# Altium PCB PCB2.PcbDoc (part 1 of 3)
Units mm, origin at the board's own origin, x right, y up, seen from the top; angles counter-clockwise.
Board outline 277.37 x 238.38 mm, 2 copper layers (Top Layer, Bottom Layer); 139 components, 149 nets, 593 pads, 86 vias.
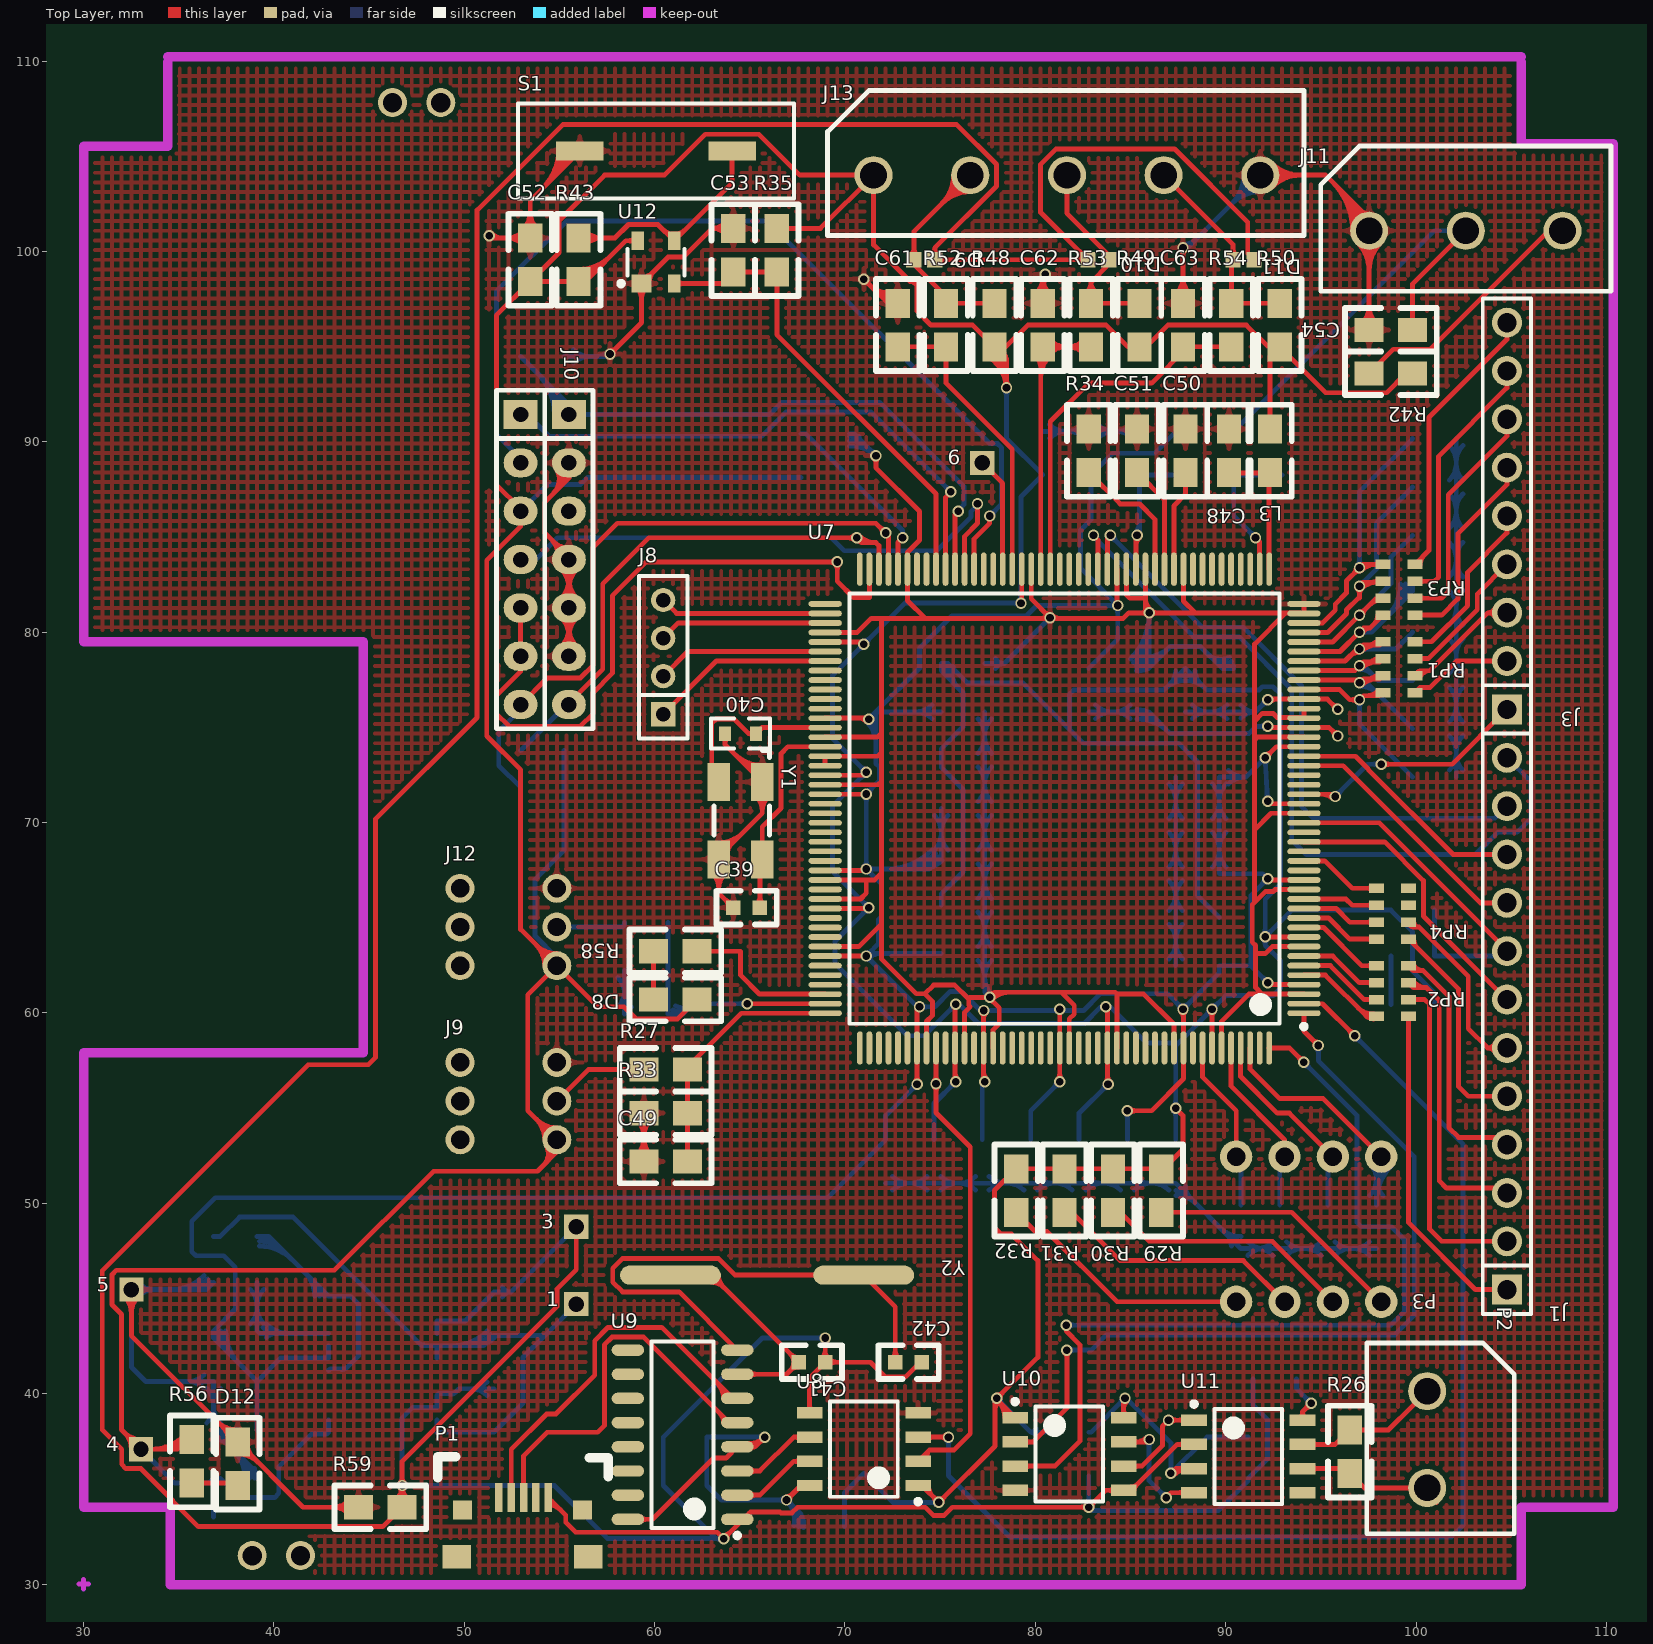
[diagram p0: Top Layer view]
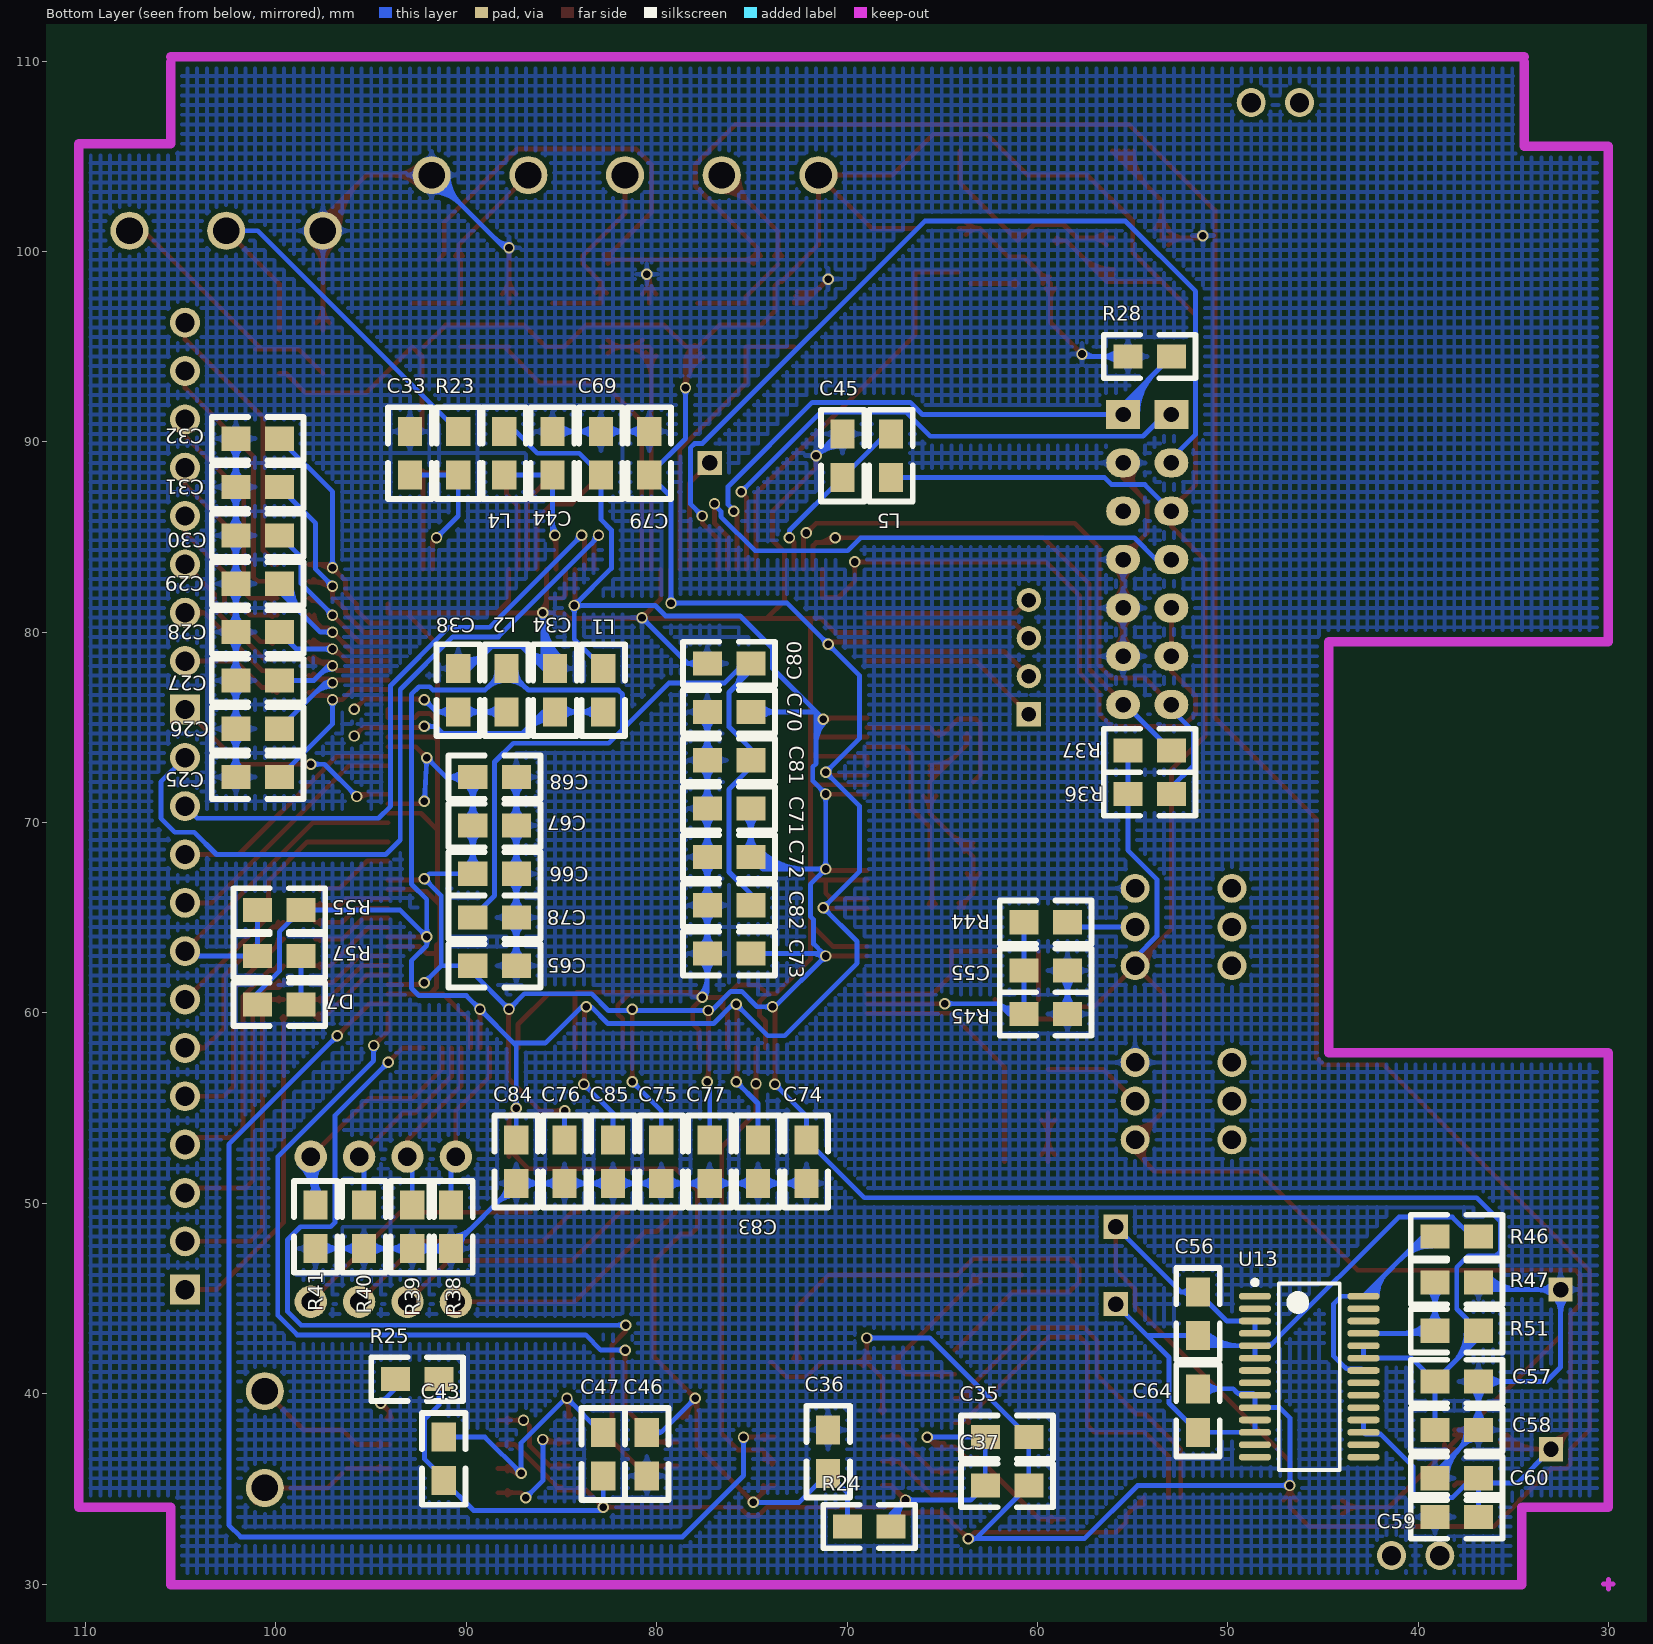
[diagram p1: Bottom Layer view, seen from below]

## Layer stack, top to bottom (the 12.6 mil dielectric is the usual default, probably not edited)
Top Layer: signal copper 0.0356
Dielectric: dielectric 0.32, FR-4, Dk 4.8
Bottom Layer: signal copper 0.0356

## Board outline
23.749,236.601 26.162,239.014 295.021,239.014 295.021,1.778 293.878,0.635 282.956,11.557 17.653,11.557

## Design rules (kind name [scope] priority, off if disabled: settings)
Clearance [All] p1: gap=0.254
PolygonConnect [All] p1: connectstyle=Relief reliefconductorwidth=0.254 reliefentries=4 polygonreliefangle="90 Angle"
RoutingVias [All] p1: holewidth=0.711 width=1.27 viastyle="Through Hole" minholewidth=0.711 minwidth=1.27 maxholewidth=0.711 maxwidth=1.27
SilkscreenOverComponentPads [All] p1: minsilkscreentomaskgap=0.254
SolderMaskExpansion [All] p1: expansion=0.102
Width [All] p1: maxlimit=0.254 minlimit=0.254 preferedwidth=0.254
27 further rules are at their usual default settings.

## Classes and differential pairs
component class Sheet1: 1 2 3 C1 C2 C3 C4 C5 C6 C7 C8 C9 C10 C11 C12 C13 C14 C15 C16 C17 C18 C19 C20 C21 C22 C23 C24 D1 D2 D3 D4 D5 D6 J1 J2 J3 J4 Q1 R1 R2 R3 R4 R5 R6 R7 R8 R9 R10 R11 R12 R13 R14 R15 R16 R17 R18 R19 R20 R21 R22 U1 U2 U3 U4 U5 U6

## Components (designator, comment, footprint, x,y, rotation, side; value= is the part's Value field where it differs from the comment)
1 "SIP1" sip-1 55.88,44.704 r90 top
3 "SIP1" sip-1 55.88,48.768 r90 top
4 "SIP1" sip-1 33.02,37.084 r90 top
5 "SIP1" sip-1 32.512,45.466 r90 top
6 "SIP1" sip-1 77.216,88.9 r270 top
C25 "Cap" 0805 102.108,72.39 r180 bottom
C26 "Cap" 0805 102.108,74.93 r180 bottom
C27 "Cap" 0805 99.822,77.47 r0 bottom
C28 "Cap" 0805 102.108,80.01 r180 bottom
C29 "Cap" 0805 102.108,82.55 r180 bottom
C30 "Cap" 0805 102.108,85.09 r180 bottom
C31 "Cap" 0805 102.108,87.63 r180 bottom
C32 "Cap" 0805 102.108,90.17 r180 bottom
C33 "Cap" 0805 92.964,90.551 r270 bottom
C34 "Cap" 0805 85.344,75.819 r90 bottom
C35 "Cap" 0805 62.738,37.719 r180 bottom
C36 "Cap" 0805 70.993,38.1 r270 bottom
C37 "Cap" 0805 62.738,35.179 r180 bottom
C38 "Cap" 0805 90.424,78.105 r270 bottom
C39 "Cap" 0603 65.532,65.532 r180 top
C40 "Cap" 0603R 64.516,74.676 r180 top
C41 "Cap" 0603 68.961,41.656 r180 top
C42 "Cap" 0603 74.041,41.656 r180 top
C43 "Cap" 0805 91.186,37.719 r270 bottom
C44 "Cap" 0805 85.471,90.551 r270 bottom
C45 "Cap" 0805 70.231,88.138 r90 bottom
C46 "Cap" 0805 80.518,35.687 r90 bottom
C47 "Cap" 0805 82.804,37.973 r270 bottom
C48 "Cap" 0805 90.17,90.678 r270 top
C49 "Cap" 0805 59.436,52.197 r0 top
C50 "Cap Pol1" 0805 87.884,88.392 r90 top
C51 "Cap Pol1" 0805 85.344,88.392 r90 top
C52 "Cap" 0805 53.467,98.425 r90 top
C53 "Cap" 0805 64.135,101.219 r270 top
C54 "Cap" 0805 97.536,95.885 r0 top
C55 "Cap" 0805 58.42,62.23 r0 bottom
C56 "Cap" 0805 51.562,45.339 r270 bottom
C57 "Cap" 0805 39.116,40.64 r180 bottom
C58 "Cap" 0805 36.83,38.1 r0 bottom
C59 "Cap" 0805 39.116,33.528 r180 bottom
C60 "Cap" 0805 39.116,35.56 r180 bottom
C61 "Cap" 0805 72.771,97.282 r270 top
C62 "Cap" 0805 80.391,97.282 r270 top
C63 "Cap" 0805 87.757,97.282 r270 top
C64 "Cap" 0805 51.562,40.259 r270 bottom
C65 "Cap" 0805 89.662,62.484 r180 bottom
C66 "Cap" 0805 87.376,67.31 r0 bottom
C67 "Cap" 0805 87.376,69.85 r0 bottom
C68 "Cap" 0805 89.662,72.39 r180 bottom
C69 "Cap" 0805 82.931,90.551 r270 bottom
C70 "Cap" 0805 77.343,75.819 r180 bottom
C71 "Cap" 0805 77.343,70.739 r180 bottom
C72 "Cap" 0805 77.343,68.199 r180 bottom
C73 "Cap" 0805 77.343,63.119 r180 bottom
C74 "Cap" 0805 72.136,51.054 r90 bottom
C75 "Cap" 0805 79.756,51.054 r90 bottom
C76 "Cap" 0805 84.836,51.054 r90 bottom
C77 "Cap" 0805 77.216,51.054 r90 bottom
C78 "Cap" 0805 87.376,65.024 r0 bottom
C79 "Cap" 0805 80.391,90.551 r270 bottom
C80 "Cap" 0805 77.343,78.359 r180 bottom
C81 "Cap" 0805 77.343,73.279 r180 bottom
C82 "Cap" 0805 77.343,65.659 r180 bottom
C83 "Cap" 0805 74.676,51.054 r90 bottom
C84 "Cap" 0805 87.376,51.054 r90 bottom
C85 "Cap" 0805 82.296,51.054 r90 bottom
D7 "LED" 0805 100.965,60.452 r180 bottom
D8 "LED" 0805 62.23,60.706 r180 top
D9 "TPD1E10B06" 0402 74.168,99.568 r0 top
D10 "TPD1E10B06" 0402 83.312,99.568 r180 top
D11 "TPD1E10B06" 0402 90.932,99.568 r0 top
D12 "LED" 0805 38.1,35.179 r90 top
J1 "SIP12" SIP12-2.54 104.775,45.466 r90 top
J3 "SIP9" SIP9-2.54 104.775,75.946 r90 top
J8 "SIP4" SIP4-2.0 60.452,75.692 r90 top
J9 "HEADER3*1" zisuo 54.864,57.404 r270 top
J10 "JTAG" JTAG-14 55.499,91.44 r270 top
J11 "HEADER3*1" 5.0J-3 97.536,101.092 r0 top
J12 "HEADER3*1" zisuo 54.864,66.548 r270 top
J13 "header5" 5.0J-5 69.088,108.712 r0 top
L1 "Inductor" 0805 82.804,78.105 r270 bottom
L2 "Inductor" 0805 87.884,78.105 r270 bottom
L3 "Inductor" 0805 92.329,90.678 r270 top
L4 "Inductor" 0805 88.011,90.551 r270 bottom
L5 "Inductor" 0805 67.691,88.138 r90 bottom
P1 "micro" micro 51.816,34.544 r0 top
P2 "Header 2" 5.0J-2 105.156,42.672 r270 top
P3 "4p" 4P 90.551,52.451 r0 top
R23 "Res2" 0805 90.424,90.551 r270 bottom
R24 "Res2" 0805 69.977,33.02 r180 bottom
R25 "Res2" 0805 91.44,40.767 r0 bottom
R26 "Res2" 0805 96.52,35.814 r90 top
R27 "Res2" 0805 59.436,57.023 r0 top
R28 "Res2" 0805 52.959,94.488 r0 bottom
R29 "Res2" 0805 86.614,49.53 r90 top
R30 "Res2" 0805 84.074,49.53 r90 top
R31 "Res2" 0805 81.534,49.53 r90 top
R32 "Res2" 0805 78.994,49.53 r90 top
R33 "Res2" 0805 59.436,54.737 r0 top
R34 "Res2" 0805 82.804,90.678 r270 top
R35 "Res2" 0805 66.421,98.933 r90 top
R36 "Res2" 0805 55.245,71.501 r180 bottom
R37 "Res2" 0805 52.959,73.787 r0 bottom
R38 "Res2" 0805 90.805,47.625 r90 bottom
R39 "Res2" 0805 92.837,47.625 r90 bottom
R40 "Res2" 0805 95.377,47.625 r90 bottom
R41 "Res2" 0805 97.917,47.625 r90 bottom
R42 "Res2" 0805 97.536,93.599 r0 top
R43 "Res2" 0805 56.007,100.711 r270 top
R44 "Res2" 0805 58.42,64.77 r0 bottom
R45 "Res2" 0805 58.42,59.944 r0 bottom
R46 "Res2" 0805 39.116,48.26 r180 bottom
R47 "Res2" 0805 36.83,45.847 r0 bottom
R48 "Res2" 0805 77.851,97.282 r270 top
R49 "Res2" 0805 85.471,97.282 r270 top
R50 "Res2" 0805 92.837,97.282 r270 top
R51 "Res2" 0805 36.83,43.307 r0 bottom
R52 "Res2" 0805 75.311,97.282 r270 top
R53 "Res2" 0805 82.931,97.282 r270 top
R54 "Res2" 0805 90.297,97.282 r270 top
R55 "Res2" 0805 100.965,65.405 r180 bottom
R56 "Res2" 0805 35.687,35.306 r90 top
R57 "Res2" 0805 100.965,62.992 r180 bottom
R58 "Res2" 0805 62.23,63.246 r180 top
R59 "Res2" 0805 46.736,34.036 r180 top
RP1 "RP" 8P4R 99.06,78.232 r180 top
RP2 "RP" 8P4R 98.806,61.087 r0 top
RP3 "RP" 8P4R 99.06,82.296 r180 top
RP4 "RP" 8P4R 98.806,65.151 r0 top
S1 "switch" "switch - duplicate" 60.071,105.283 r180 top
U7 "TMS320F28335" PTP 81.534,70.739 r180 top
U8 "ISO7221" SO-8 70.993,37.084 r180 top
U9 "CH340G" SOP16 61.468,37.846 r180 top
U10 "ISO7221" SO-8 81.788,36.83 r0 top
U11 "SN65HVD230" SO-8 91.186,36.703 r0 top
U12 "MAX811" SOT143 60.071,99.441 r90 top
U13 "TPS767D301" TPS767 45.72,40.894 r180 bottom
Y1 "crystal" 5032 66.04,72.136 r270 top
Y2 "CRYSTAL" 49SMD 60.833,46.228 r0 top

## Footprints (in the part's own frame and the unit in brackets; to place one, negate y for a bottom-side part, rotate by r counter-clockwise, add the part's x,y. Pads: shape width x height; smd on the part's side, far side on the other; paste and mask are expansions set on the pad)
4P [mm]
  round 1.7 hole 0.97: 1(0,0) 2(2.54,0) 3(5.08,0) 4(7.62,0) 5(7.62,-7.62) 6(5.08,-7.62) 7(2.54,-7.62) 8(0,-7.62)
5.0J-2 [mm]
  round 2 hole 1.4: 1(2.54,-4.572) 2(7.62,-4.572)
  silkscreen extent 0,-7.75 10.03,0
5.0J-3 [mm]
  round 2 hole 1.4: 1(0,0) 2(5.08,0) 3(10.16,0)
  silkscreen extent -2.54,-3.17 12.7,4.44
5.0J-5 [mm]
  round 2 hole 1.4: 1(2.413,-4.699) 2(7.493,-4.699) 3(12.573,-4.699) 4(17.653,-4.699) 5(22.733,-4.699)
  silkscreen extent 0,-7.87 25.02,-0.25
8P4R [mm]
  rect 0.8x0.5 smd: 1(-0.889,1.397) 2(-0.889,0.508) 3(-0.889,-0.381) 4(-0.889,-1.27) 5(0.8,-1.27) 6(0.8,-0.381) 7(0.8,0.508) 8(0.8,1.397)
49SMD [mm]
  oval 5.3x1 smd: 1(0,0) 3(10.15,0)
0402 [mm] "Chip Resistor, 2-Leads, Body 1.0x0.6mm, IPC Medium Density"
  rect 0.8x0.8 smd: 1(-0.55,0) 2(0.55,0)
0603 [mil]
  rect 30x30 smd: 1(0,0) 2(55,0)
  silkscreen extent -35,-35 90,35
0603R [mil]
  rect 25x30 smd: 1(-32,0) 2(32,0)
  silkscreen extent -61,-31 61,31
0805 [mil]
  rect 60x50 smd: 1(0,0) 2(90,0)
  silkscreen extent -50,-45 140,45
5032 [mm]
  rect 2x1.2 smd: 1(0,-2.667) 2(4.064,-2.667) 3(4.064,-0.381) 4(0,-0.381)
  silkscreen extent -1.65,-2.92 2.79,0
JTAG-14 [mil]
  rect 60x70 hole 32: 1(0,-100) 2(0,0)
  oval 60x70 hole 32: 3(100,-100) 4(100,0) 5(200,-100) 6(200,0) 7(300,-100) 8(300,0) 9(400,-100) 10(400,0) 11(500,-100) 12(500,0) 13(600,-100) 14(600,0)
  silkscreen extent -50,-150 650,50
micro [mm]
  rect 1.5x1.23 smd: 0(-2.2,-3.1) 0(4.7,-3.1)
  rect 1x1 smd: 0(-1.9,-0.65) 0(4.4,-0.65)
  rect 0.4x1.524 smd: 1(0,0) 2(0.65,0) 3(1.3,0) 4(1.95,0) 5(2.6,0)
  silkscreen extent -3.2,1.05 5.75,2.15
PTP [mm] "TSQFP, 176-Leads, Body 26.2x26.2mm (max), Pitch 0.50mm, IPC Medium Density"
  oval 1.75x0.3 smd: 1(-12.575,10.75) 2(-12.575,10.25) 3(-12.575,9.75) 4(-12.575,9.25) 5(-12.575,8.75) 6(-12.575,8.25) 7(-12.575,7.75) 8(-12.575,7.25) 9(-12.575,6.75) 10(-12.575,6.25) 11(-12.575,5.75) 12(-12.575,5.25) 13(-12.575,4.75) 14(-12.575,4.25) 15(-12.575,3.75) 16(-12.575,3.25) 17(-12.575,2.75) 18(-12.575,2.25) 19(-12.575,1.75) 20(-12.575,1.25) 21(-12.575,0.75) 22(-12.575,0.25) 23(-12.575,-0.25) 24(-12.575,-0.75) 25(-12.575,-1.25) 26(-12.575,-1.75) 27(-12.575,-2.25) 28(-12.575,-2.75) 29(-12.575,-3.25) 30(-12.575,-3.75) 31(-12.575,-4.25) 32(-12.575,-4.75) 33(-12.575,-5.25) 34(-12.575,-5.75) 35(-12.575,-6.25) 36(-12.575,-6.75) 37(-12.575,-7.25) 38(-12.575,-7.75) 39(-12.575,-8.25) 40(-12.575,-8.75) 41(-12.575,-9.25) 42(-12.575,-9.75) 43(-12.575,-10.25) 44(-12.575,-10.75) 89(12.575,-10.75) 90(12.575,-10.25) 91(12.575,-9.75) 92(12.575,-9.25) 93(12.575,-8.75) 94(12.575,-8.25) 95(12.575,-7.75) 96(12.575,-7.25) 97(12.575,-6.75) 98(12.575,-6.25) 99(12.575,-5.75) 100(12.575,-5.25) 101(12.575,-4.75) 102(12.575,-4.25) 103(12.575,-3.75) 104(12.575,-3.25) 105(12.575,-2.75) 106(12.575,-2.25) 107(12.575,-1.75) 108(12.575,-1.25) 109(12.575,-0.75) 110(12.575,-0.25) 111(12.575,0.25) 112(12.575,0.75) 113(12.575,1.25) 114(12.575,1.75) 115(12.575,2.25) 116(12.575,2.75) 117(12.575,3.25) 118(12.575,3.75) 119(12.575,4.25) 120(12.575,4.75) 121(12.575,5.25) 122(12.575,5.75) 123(12.575,6.25) 124(12.575,6.75) 125(12.575,7.25) 126(12.575,7.75) 127(12.575,8.25) 128(12.575,8.75) 129(12.575,9.25) 130(12.575,9.75) 131(12.575,10.25) 132(12.575,10.75)
  oval 0.3x1.75 smd: 45(-10.75,-12.575) 46(-10.25,-12.575) 47(-9.75,-12.575) 48(-9.25,-12.575) 49(-8.75,-12.575) 50(-8.25,-12.575) 51(-7.75,-12.575) 52(-7.25,-12.575) 53(-6.75,-12.575) 54(-6.25,-12.575) 55(-5.75,-12.575) 56(-5.25,-12.575) 57(-4.75,-12.575) 58(-4.25,-12.575) 59(-3.75,-12.575) 60(-3.25,-12.575) 61(-2.75,-12.575) 62(-2.25,-12.575) 63(-1.75,-12.575) 64(-1.25,-12.575) 65(-0.75,-12.575) 66(-0.25,-12.575) 67(0.25,-12.575) 68(0.75,-12.575) 69(1.25,-12.575) 70(1.75,-12.575) 71(2.25,-12.575) 72(2.75,-12.575) 73(3.25,-12.575) 74(3.75,-12.575) 75(4.25,-12.575) 76(4.75,-12.575) 77(5.25,-12.575) 78(5.75,-12.575) 79(6.25,-12.575) 80(6.75,-12.575) 81(7.25,-12.575) 82(7.75,-12.575) 83(8.25,-12.575) 84(8.75,-12.575) 85(9.25,-12.575) 86(9.75,-12.575) 87(10.25,-12.575) 88(10.75,-12.575) 133(10.75,12.575) 134(10.25,12.575) 135(9.75,12.575) 136(9.25,12.575) 137(8.75,12.575) 138(8.25,12.575) 139(7.75,12.575) 140(7.25,12.575) 141(6.75,12.575) 142(6.25,12.575) 143(5.75,12.575) 144(5.25,12.575) 145(4.75,12.575) 146(4.25,12.575) 147(3.75,12.575) 148(3.25,12.575) 149(2.75,12.575) 150(2.25,12.575) 151(1.75,12.575) 152(1.25,12.575) 153(0.75,12.575) 154(0.25,12.575) 155(-0.25,12.575) 156(-0.75,12.575) 157(-1.25,12.575) 158(-1.75,12.575) 159(-2.25,12.575) 160(-2.75,12.575) 161(-3.25,12.575) 162(-3.75,12.575) 163(-4.25,12.575) 164(-4.75,12.575) 165(-5.25,12.575) 166(-5.75,12.575) 167(-6.25,12.575) 168(-6.75,12.575) 169(-7.25,12.575) 170(-7.75,12.575) 171(-8.25,12.575) 172(-8.75,12.575) 173(-9.25,12.575) 174(-9.75,12.575) 175(-10.25,12.575) 176(-10.75,12.575)
  silkscreen extent -12.7,-11.3 11.3,11.57
SIP4-2.0 [mil]
  rect 50x50 hole 30: 1(0,0)
  round 50 hole 30: 2(78.74,0) 3(157.48,0) 4(236.22,0)
  silkscreen extent -50,-50 286,50
SIP9-2.54 [mil]
  rect 62x62 hole 40: 1(0,0)
  round 62 hole 40: 2(100,0) 3(200,0) 4(300,0) 5(400,0) 6(500,0) 7(600,0) 8(700,0) 9(800,0)
  silkscreen extent -50,-50 850,50
SIP12-2.54 [mil]
  rect 62x62 hole 40: 1(0,0)
  round 62 hole 40: 2(100,0) 3(200,0) 4(300,0) 5(400,0) 6(500,0) 7(600,0) 8(700,0) 9(800,0) 10(900,0) 11(1000,0) 12(1100,0)
  silkscreen extent -50,-50 1150,50
sip-1 [mil]
  rect 50x50 hole 32: 1(0,0)
SO-8 [mm] "SOIC, 8-Leads, Body 5.0x4.0mm (max), Pitch 1.27mm, IPC Medium Density"
  rect 1.35x0.6 smd: 1(-2.85,1.905) 2(-2.85,0.635) 3(-2.85,-0.635) 4(-2.85,-1.905) 5(2.85,-1.905) 6(2.85,-0.635) 7(2.85,0.635) 8(2.85,1.905)
  silkscreen extent -2.98,-2.5 1.78,2.88
SOP16 [mm]
  oval 1.7x0.6 smd: 1(-2.875,4.445) 2(-2.875,3.175) 3(-2.875,1.905) 4(-2.875,0.635) 5(-2.875,-0.635) 6(-2.875,-1.905) 7(-2.875,-3.175) 8(-2.875,-4.445) 9(2.875,-4.445) 10(2.875,-3.175) 11(2.875,-1.905) 12(2.875,-0.635) 13(2.875,0.635) 14(2.875,1.905) 15(2.875,3.175) 16(2.875,4.445)
  silkscreen extent -3,-4.9 1.63,5.42
SOT143 [mm] "SOT143, 4-Leads, Body 3.0x2.5mm (max), Pitch 1.92mm, IPC Medium Density"
  rect 0.95x1.05 smd: 1(-1.125,0.76)
  rect 0.95x0.65 smd: 2(-1.125,-0.96) 3(1.125,-0.96) 4(1.125,0.96)
  silkscreen extent -1.25,-1.5 0.7,1.96
"switch - duplicate" [mm]
  rect 2.5x1 smd: 1(-4,0) 2(4,0)
  silkscreen extent -7.25,-2.5 7.25,2.5
TPS767 [mm]
  oval 1.7x0.35 smd: 1(-2.85,4.225) 2(-2.85,3.575) 3(-2.85,2.925) 4(-2.85,2.275) 5(-2.85,1.625) 6(-2.85,0.975) 7(-2.85,0.325) 8(-2.85,-0.325) 9(-2.85,-0.975) 10(-2.85,-1.625) 11(-2.85,-2.275) 12(-2.85,-2.925) 13(-2.85,-3.575) 14(-2.85,-4.225) 15(2.85,-4.225) 16(2.85,-3.575) 17(2.85,-2.925) 18(2.85,-2.275) 19(2.85,-1.625) 20(2.85,-0.975) 21(2.85,-0.325) 22(2.85,0.325) 23(2.85,0.975) 24(2.85,1.625) 25(2.85,2.275) 26(2.85,2.925) 27(2.85,3.575) 28(2.85,4.225)
  silkscreen extent -2.98,-4.9 1.6,5.07
zisuo [mil]
  round 60 hole 38.19: 1(0,0) 2(80,0) 3(160,0) 4(0,-200) 5(80,-200) 6(160,-200)

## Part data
1 3 4 5 6: "Variable Resistor"
C25 C26 C27 C28 C29 C30 C31 C32 C33 C34 C35 C36 C37 C38 C39 C40 C41 C42 C43 C44 C45 C46 C47 C48 C49 C52 C53 C54 C55 C56 C57 C58 C59 C60 C61 C62 C63 C64 C65 C66 C67 C68 C69 C70 C71 C72 C73 C74 C75 C76 C77 C78 C79 C80 C81 C82 C83 C84 C85: "Capacitor"
C50 C51: "Polarized Capacitor (Radial)"
J1 J3 J8: "jointbar"
P2: "Header, 2-Pin"
R23 R24 R25 R26 R27 R28 R29 R30 R31 R32 R33 R34 R35 R36 R37 R38 R39 R40 R41 R42 R43 R44 R45 R46 R47 R48 R49 R50 R51 R52 R53 R54 R55 R56 R57 R58 R59: "Resistor"

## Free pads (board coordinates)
  round 1.524 hole 1.016: 0(38.862,31.496) 0(46.228,107.823) 1(41.402,31.496) 1(48.768,107.823)

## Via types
v1: diameter 0.6, hole 0.4, Top Layer to Bottom Layer, 86 vias

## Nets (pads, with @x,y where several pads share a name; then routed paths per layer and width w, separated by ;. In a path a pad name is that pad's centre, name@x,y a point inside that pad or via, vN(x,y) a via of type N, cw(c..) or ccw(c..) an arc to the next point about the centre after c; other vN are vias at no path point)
1V9: C57.1 C58.2 C65.1 C66.2 C67.2 C68.1 C69.2 C70.2 C71.2 C72.2 C73.2 C74.2 C75.2 C76.2 C77.2 L1.1 L4.1 R51.1 U7.4 U7.15 U7.23 U7.29 U7.61 U7.101 U7.109 U7.117 U7.126 U7.139 U7.146 U7.154 U7.167 U13.23 U13.24 | length 309.6
  Top Layer w0.254: U7.126@68.959,62.989 v1@71.117,62.989 ; U7.117@68.959,67.489 v1@71.045,67.489 ; U7.109@68.959,71.489 v1@71.108,71.489 ; U7.101@68.959,75.489 v1@71.196,75.489 ; v1@73.784,56.264 U7.139@73.784,58.164 v1@73.784,60.195 ; v1@77.284,56.447 U7.146@77.284,58.164 v1(77.284,60.13) ; v1@81.284,56.392 U7.154@81.284,58.164 v1@81.284,60.194 ; v1@84.284,81.451 U7.61@84.284,83.314 ; v1(84.836,54.864) 86.106,54.864 87.784,56.542 U7.167@87.784,58.164 v1@87.784,60.171 ; v1(92.075,73.406) 92.658,73.989 U7.29@94.109,73.989 ; v1@92.269,66.989 U7.15@94.109,66.989 ; v1@92.308,61.489 U7.4@94.109,61.489 ; v1@92.333,70.989 U7.23@94.109,70.989 ; 77.284,59.712 cw(c77.702,59.712) 77.406,60.008 ccw(c77.702,59.712) 77.284,59.712 ; 77.284,59.712 ccw(c76.866,59.712) 77.162,60.008 cw(c76.866,59.712) 77.284,59.712 ; 85.254,54.864 cw(c85.254,55.282) 84.958,54.986 ccw(c85.254,55.282) 85.254,54.864 ; 85.254,54.864 ccw(c85.254,54.446) 84.958,54.742 cw(c85.254,54.446) 85.254,54.864 ; 92.37,73.701 cw(c92.075,73.997) 92.075,73.579 ccw(c92.075,73.997) 92.37,73.701 ; 92.37,73.701 ccw(c92.666,73.406) 92.248,73.406 cw(c92.666,73.406) 92.37,73.701 ; 70.706,75.489 cw(c70.706,74.897) 71.125,75.316 ccw(c70.706,74.897) 70.706,75.489 ; v1@73.665,56.383 ccw(c73.377,56.671) 73.784,56.671 cw(c73.377,56.671) v1@73.665,56.383 ; 73.784,56.686 ccw(c74.212,56.686) 73.909,56.383 cw(c74.212,56.686) 73.784,56.686 ; 77.284,56.948 ccw(c77.903,56.948) 77.465,56.51 cw(c77.903,56.948) 77.284,56.948 ; v1@81.158,56.51 ccw(c80.853,56.815) 81.284,56.815 cw(c80.853,56.815) v1@81.158,56.51 ; 81.284,56.796 ccw(c81.688,56.796) 81.402,56.51 cw(c81.688,56.796) 81.284,56.796 ; v1@87.635,60.076 cw(c87.274,59.715) 87.784,59.715 ccw(c87.274,59.715) v1@87.635,60.076 ; 87.784,59.846 cw(c88.109,59.846) 87.879,60.076 ccw(c88.109,59.846) 87.784,59.846
  Bottom Layer w0.254: C58.2@39.116,38.1 C57.1@39.116,40.64 ; U13.24@42.87,42.519 U13.23@42.87,41.869 40.345,41.869 C57.1@39.116,40.64 ; v1(71.247,75.438) 71.628,75.819 ; v1(73.787,56.261) 72.136,54.61 C74.2@72.136,53.34 69.088,50.292 36.926,50.292 35.687,49.053 35.687,47.467 35.91,47.244 37.369,47.244 37.973,46.64 37.973,44.45 R51.1@36.83,43.307 36.83,42.926 C57.1@39.116,40.64 ; C73.2@75.057,63.119 v1@71.247,63.119 ; C71.2@75.057,70.739 C72.2@75.057,68.199 74.422,67.564 v1(71.12,67.564) ; C70.2@75.057,75.819 71.628,75.819 ; C77.2@77.216,53.34 v1@77.216,56.261 ; C75.2@79.756,53.34 79.756,54.864 v1(81.28,56.388) ; L1.1@82.804,78.105 84.328,79.629 v1(84.328,81.407) ; C76.2@84.836,53.34 v1(84.836,54.864) ; L4.1@88.011,90.551 87.407,90.551 86.264,89.408 84.074,89.408 C69.2@82.931,88.265 82.931,85.926 82.377,85.372 82.377,83.358 v1(84.328,81.407) ; v1(92.202,61.595) 91.313,62.484 ; v1(92.202,71.12) v1(92.075,73.406) 91.059,72.39 C68.1@89.662,72.39 C67.2@89.662,69.85 C66.2@89.662,67.31 91.948,67.31 v1(92.202,67.056) 91.313,66.167 91.313,62.484 ; v1(71.12,67.564) 71.928,66.756 71.928,65.077 71.755,64.904 71.755,63.627 v1@71.247,63.119 ; v1(71.12,67.564) v1(71.12,71.501) 71.12,71.508 71.801,72.189 71.801,72.926 71.628,73.099 71.628,75.819 ; 71.12,67.982 cw(c70.702,67.982) 70.998,67.686 ccw(c70.702,67.982) 71.12,67.982 ; 71.12,67.982 ccw(c71.538,67.982) v1@71.242,67.686 ; 71.12,67.982 ccw(c71.538,67.982) v1@71.242,67.686 ; 71.12,71.083 cw(c71.538,71.083) 71.242,71.379 ccw(c71.538,71.083) 71.12,71.083 ; 71.12,71.083 ccw(c70.702,71.083) 70.998,71.379 cw(c70.702,71.083) 71.12,71.083 ; v1@71.242,67.686 ccw(c71.538,67.982) 71.538,67.564 ; v1@71.242,67.686 ccw(c71.538,67.982) 71.538,67.564 ; v1@71.247,63.119 v1(71.12,62.992) 73.787,60.325 v1(73.914,60.325) 74.729,60.325 75.537,61.133 76.101,61.133 77.104,60.13 v1(77.284,60.13) 82.535,60.13 83.411,61.006 86.949,61.006 v1(87.757,60.198) 89.662,62.103 C65.1@89.662,62.484 91.313,62.484 ; v1@71.293,62.992 ccw(c71.711,62.992) 71.415,62.697 ; v1@71.293,62.992 cw(c71.711,62.992) 71.415,63.287 ; v1@71.293,62.992 cw(c71.711,62.992) 71.415,63.287 ; v1@71.293,62.992 ccw(c71.711,62.992) 71.415,62.697 ; 71.415,62.697 ccw(c71.12,62.401) 71.12,62.819 cw(c71.12,62.401) 71.415,62.697 ; 71.415,63.287 cw(c71.12,63.583) 71.12,63.165 ccw(c71.12,63.583) 71.415,63.287 ; 71.415,67.269 cw(c71.711,67.564) 71.293,67.564 ccw(c71.711,67.564) 71.415,67.269 ; 71.415,67.269 ccw(c71.12,66.973) 71.12,67.391 cw(c71.12,66.973) 71.415,67.269 ; 71.538,67.564 ccw(c71.538,67.146) 71.242,67.442 cw(c71.538,67.146) 71.538,67.564 ; 71.628,75.819 73.914,78.105 73.914,79.152 75.615,80.853 79.53,80.853 80.084,81.407 v1(84.328,81.407) ; 73.492,55.966 cw(c73.787,55.67) 73.787,56.088 ccw(c73.787,55.67) 73.492,55.966 ; 73.492,55.966 ccw(c73.196,56.261) 73.614,56.261 cw(c73.196,56.261) 73.492,55.966 ; 73.704,75.819 cw(c73.704,74.593) 74.571,75.46 ccw(c73.704,74.593) 73.704,75.819 ; 73.704,75.819 ccw(c73.704,77.045) 74.571,76.178 cw(c73.704,77.045) 73.704,75.819 ; 74.332,60.325 cw(c74.332,60.743) 74.036,60.447 ccw(c74.332,60.743) 74.332,60.325 ; 74.332,60.325 ccw(c74.332,59.907) 74.036,60.203 cw(c74.332,59.907) 74.332,60.325 ; 75.057,69.425 cw(c73.831,69.425) 74.698,68.558 ccw(c73.831,69.425) 75.057,69.425 ; 75.057,69.425 ccw(c76.283,69.425) 75.416,68.558 cw(c76.283,69.425) 75.057,69.425 ; 75.057,69.513 cw(c76.283,69.513) 75.416,70.38 ccw(c76.283,69.513) 75.057,69.513 ; 75.057,69.513 ccw(c73.831,69.513) 74.698,70.38 cw(c73.831,69.513) 75.057,69.513 ; 80.985,56.093 cw(c81.28,55.797) 81.28,56.215 ccw(c81.28,55.797) 80.985,56.093 ; 80.985,56.093 ccw(c80.689,56.388) 81.107,56.388 cw(c80.689,56.388) 80.985,56.093 ; 83.91,81.407 cw(c83.91,80.989) v1@84.206,81.285 ; 83.91,81.407 ccw(c83.91,81.825) 84.206,81.529 cw(c83.91,81.825) 83.91,81.407 ; 83.91,81.407 cw(c83.91,80.989) v1@84.206,81.285 ; 84.033,81.702 cw(c83.737,81.407) 84.155,81.407 ccw(c83.737,81.407) 84.033,81.702 ; 84.033,81.702 ccw(c84.328,81.998) 84.328,81.58 cw(c84.328,81.998) 84.033,81.702 ; v1@84.206,81.285 cw(c83.91,80.989) 84.328,80.989 ; v1@84.206,81.285 cw(c83.91,80.989) 84.328,80.989 ; 84.328,80.989 cw(c84.746,80.989) 84.45,81.285 ccw(c84.746,80.989) 84.328,80.989 ; 84.836,54.446 cw(c85.254,54.446) 84.958,54.742 ccw(c85.254,54.446) 84.836,54.446 ; 84.836,54.446 ccw(c84.418,54.446) 84.714,54.742 cw(c84.418,54.446) 84.836,54.446 ; 87.462,60.493 cw(c87.166,60.198) 87.584,60.198 ccw(c87.166,60.198) 87.462,60.493 ; 87.462,60.493 ccw(c87.757,60.789) v1@87.757,60.371 ; 87.462,60.493 ccw(c87.757,60.789) v1@87.757,60.371 ; v1@87.757,60.371 ccw(c87.757,60.789) 88.052,60.493 ; v1@87.757,60.371 ccw(c87.757,60.789) 88.052,60.493 ; 88.052,60.493 ccw(c88.348,60.198) 87.93,60.198 cw(c88.348,60.198) 88.052,60.493 ; 89.662,68.536 cw(c88.436,68.536) 89.303,67.669 ccw(c88.436,68.536) 89.662,68.536 ; 89.662,68.536 ccw(c90.888,68.536) 90.021,67.669 cw(c90.888,68.536) 89.662,68.536 ; 89.662,68.624 cw(c90.888,68.624) 90.021,69.491 ccw(c90.888,68.624) 89.662,68.624 ; 89.662,68.624 ccw(c88.436,68.624) 89.303,69.491 cw(c88.436,68.624) 89.662,68.624 ; 89.662,71.076 cw(c88.436,71.076) 89.303,70.209 ccw(c88.436,71.076) 89.662,71.076 ; 89.662,71.076 ccw(c90.888,71.076) 90.021,70.209 cw(c90.888,71.076) 89.662,71.076 ; 89.662,71.164 cw(c90.888,71.164) 90.021,72.031 ccw(c90.888,71.164) 89.662,71.164 ; 89.662,71.164 ccw(c88.436,71.164) 89.303,72.031 cw(c88.436,71.164) 89.662,71.164 ; 91.015,72.39 cw(c91.015,73.616) 90.148,72.749 ccw(c91.015,73.616) 91.015,72.39 ; 91.015,72.39 ccw(c91.015,71.164) 90.148,72.031 cw(c91.015,71.164) 91.015,72.39 ; 91.78,73.111 cw(c92.075,72.815) 92.075,73.233 ccw(c92.075,72.815) 91.78,73.111 ; 91.78,73.111 ccw(c91.484,73.406) 91.902,73.406 cw(c91.484,73.406) 91.78,73.111 ; 91.907,61.89 cw(c91.611,61.595) 92.029,61.595 ccw(c91.611,61.595) 91.907,61.89 ; 91.907,61.89 ccw(c92.202,62.186) 92.202,61.768 cw(c92.202,62.186) 91.907,61.89 ; 91.907,66.761 cw(c92.202,66.465) 92.202,66.883 ccw(c92.202,66.465) 91.907,66.761 ; 91.907,66.761 ccw(c91.611,67.056) 92.029,67.056 cw(c91.611,67.056) 91.907,66.761 ; 92.098,72.989 cw(c92.515,73.012) 92.204,73.291 ccw(c92.515,73.012) 92.098,72.989 ; 92.098,72.989 ccw(c91.681,72.966) 91.96,73.277 cw(c91.681,72.966) 92.098,72.989 ; 92.179,71.537 cw(c91.762,71.514) 92.073,71.235 ccw(c91.762,71.514) 92.179,71.537 ; 92.179,71.537 ccw(c92.596,71.56) 92.317,71.249 cw(c92.596,71.56) 92.179,71.537 ; R51.1@36.957,43.307 ccw(c38.183,43.307) 37.316,42.44 cw(c38.183,43.307) R51.1@36.957,43.307 ; R51.1@37.211,43.307 ccw(c39.051,43.307) 37.75,42.006 cw(c39.051,43.307) R51.1@37.211,43.307 ; R51.1@37.465,43.307 ccw(c39.918,43.307) 38.183,41.573 cw(c39.918,43.307) R51.1@37.465,43.307 ; v1@71.12,71.674 ccw(c71.12,72.075) 71.404,71.791 cw(c71.12,72.075) v1@71.12,71.674 ; v1@71.125,75.316 cw(c69.91,74.101) 71.628,74.101 ccw(c69.91,74.101) v1@71.125,75.316 ; v1@71.242,62.87 cw(c71.844,62.268) 71.844,63.119 ccw(c71.844,62.268) v1@71.242,62.87 ; v1@71.293,71.501 cw(c71.727,71.501) 71.42,71.808 ccw(c71.727,71.501) v1@71.293,71.501 ; v1@71.304,75.495 cw(c70.523,74.714) 71.628,74.714 ccw(c70.523,74.714) v1@71.304,75.495 ; 71.484,75.675 cw(c71.136,75.327) 71.628,75.327 ccw(c71.136,75.327) 71.484,75.675 ; 72.171,67.564 ccw(c72.171,70.958) 74.571,68.558 cw(c72.171,70.958) 72.171,67.564 ; 72.784,67.564 ccw(c72.784,70.345) 74.75,68.379 cw(c72.784,70.345) 72.784,67.564 ; 73.397,67.564 ccw(c73.397,69.732) 74.93,68.199 cw(c73.397,69.732) 73.397,67.564 ; 74.01,67.564 ccw(c74.01,69.119) 75.11,68.019 cw(c74.01,69.119) 74.01,67.564
  other v1: 77.343,56.388 81.28,60.198
3.3V-D: 
3V3: 4.1 C36.2 C46.2 C52.1 C59.2 C60.2 C78.2 C79.2 C80.2 C81.2 C82.2 C83.2 C84.2 C85.2 D7.1 D8.1 J9.3 J10.5 J12.3 J13.1 L2.1 L3.1 L5.1 R24.1 R29.2 R30.2 R31.2 R32.2 R35.2 R36.1 R37.2 R42.2 R43.2 R48.2 R49.2 R50.2 R55.2 R56.2 U7.9 U7.71 U7.93 U7.107 U7.121 U7.143 U7.159 U7.170 U8.1 U10.1 U12.4 U13.17 U13.18 | length 566
  Top Layer w0.254: 4.1@32.512,37.084 ccw(c31.286,37.084) 32.153,37.951 ccw(c33.02,38.818) 4.1@33.02,37.592 ; 4.1@33.541,37.084 ccw(c33.541,39.611) R56.2@35.328,37.824 ; 34.154,37.084 ccw(c34.154,38.998) R56.2@35.507,37.645 ; 34.767,37.084 ccw(c34.767,38.385) R56.2@35.687,37.465 ; 34.983,37.142 cw(c35.344,36.781) R56.2@35.573,37.238 ; R56.2@35.089,37.248 ccw(c34.872,37.465) R56.2@35.179,37.465 ; R56.2@35.433,37.592 34.925,37.084 4.1@33.02,37.084 31.994,38.11 31.994,44.175 31.496,44.673 31.496,46.259 31.719,46.482 43.18,46.482 48.387,51.689 53.848,51.689 54.864,52.705 J9.3@54.864,53.34 53.34,54.864 53.34,60.96 J12.3@54.864,62.484 ; U12.4@59.111,100.566 58.491,100.566 56.35,98.425 R43.2@56.007,98.425 C52.1@53.467,98.425 ; D8.1@62.23,60.706 61.214,59.69 59.024,59.69 58.389,60.325 57.023,60.325 J12.3@54.864,62.484 ; R35.2@66.421,101.219 68.707,101.219 J13.1@71.501,104.013 ; U7.121@68.959,65.489 v1@71.204,65.489 ; U7.107@68.959,72.489 v1@70.965,72.489 ; U7.93@68.959,79.489 v1@70.879,79.489 ; U8.1@73.843,35.179 74.041,35.179 v1(74.93,34.29) 77.882,37.242 77.882,39.655 v1(77.978,39.751) 80.137,41.91 80.137,46.99 78.74,48.387 78.201,48.387 77.851,48.737 77.851,50.673 R32.2@78.994,51.816 R31.2@81.534,51.816 R30.2@84.074,51.816 R29.2@86.614,51.816 86.741,51.816 87.757,52.832 ; v1@75.784,56.423 U7.143@75.784,58.164 v1@75.784,60.417 ; v1@77.978,39.695 U10.1@78.938,38.735 ; v1(78.486,92.837) 78.486,94.361 R48.2@77.851,94.996 ; v1@79.284,81.57 U7.71@79.284,83.314 ; v1@83.784,56.297 U7.159@83.784,58.164 v1@83.784,60.234 ; v1(87.376,54.991) 87.757,54.61 87.757,52.832 ; 87.757,52.451 87.757,52.832 ; U7.170@89.284,58.164 v1@89.284,60.195 ; v1@92.094,63.989 U7.9@94.109,63.989 ; R50.2@92.233,94.996 91.09,96.139 86.964,96.139 85.821,94.996 84.867,94.996 83.724,96.139 79.598,96.139 78.455,94.996 R48.2@77.851,94.996 ; L3.1@92.329,90.678 92.329,94.488 R50.2@92.837,94.996 93.844,93.989 ; 93.98,93.853 93.844,93.989 ; R42.2@99.822,93.599 99.472,93.599 98.456,92.583 95.25,92.583 93.844,93.989 ; C52.1@53.467,98.425 51.689,96.647 51.689,87.757 52.959,86.487 J10.5@52.959,86.36 52.959,85.563 51.181,83.785 51.181,74.549 52.959,72.771 52.959,64.389 J12.3@54.864,62.484 ; C52.1@53.467,98.425 54.991,99.949 54.991,101.631 57.373,104.013 60.512,104.013 62.663,106.164 65.479,106.164 67.63,104.013 J13.1@71.501,104.013 ; 53.78,54.424 cw(c52.696,53.34) 54.229,53.34 ccw(c52.696,53.34) 53.78,54.424 ; 53.78,54.424 ccw(c54.864,55.508) 54.864,53.975 cw(c54.864,55.508) 53.78,54.424 ; 53.78,63.568 cw(c52.696,62.484) 54.229,62.484 ccw(c52.696,62.484) 53.78,63.568 ; 53.78,63.568 ccw(c54.864,64.652) 54.864,63.119 cw(c54.864,64.652) 53.78,63.568 ; 54.214,53.99 cw(c53.563,53.34) 54.483,53.34 ccw(c53.563,53.34) 54.214,53.99 ; 54.214,53.99 ccw(c54.864,54.641) 54.864,53.721 cw(c54.864,54.641) 54.214,53.99 ; 54.214,63.134 cw(c53.563,62.484) 54.483,62.484 ccw(c53.563,62.484) 54.214,63.134 ; 54.214,63.134 ccw(c54.864,63.785) 54.864,62.865 cw(c54.864,63.785) 54.214,63.134 ; 58.633,100.566 cw(c58.633,100.088) 58.971,100.426 ccw(c58.633,100.088) 58.633,100.566 ; 58.633,100.566 ccw(c58.633,101.044) 58.971,100.706 cw(c58.633,101.044) 58.633,100.566 ; J13.1@71.501,104.013 71.501,100.346 73.422,98.425 73.564,98.425 73.787,98.202 73.787,96.87 74.518,96.139 76.708,96.139 R48.2@77.851,94.996 ; 74.635,34.585 cw(c74.339,34.29) 74.757,34.29 ccw(c74.339,34.29) 74.635,34.585 ; 74.635,34.585 ccw(c74.93,34.881) v1@74.93,34.463 ; 74.635,34.585 ccw(c74.93,34.881) v1@74.93,34.463 ; v1@74.93,34.463 ccw(c74.93,34.881) 75.225,34.585 ; v1@74.93,34.463 ccw(c74.93,34.881) 75.225,34.585 ; 75.225,34.585 ccw(c75.521,34.29) 75.103,34.29 cw(c75.521,34.29) 75.225,34.585 ; 78.273,40.046 cw(c77.978,40.342) 77.978,39.924 ccw(c77.978,40.342) 78.273,40.046 ; 78.273,40.046 ccw(c78.569,39.751) 78.151,39.751 cw(c78.569,39.751) 78.273,40.046 ; 78.486,93.255 cw(c78.068,93.255) 78.364,92.959 ccw(c78.068,93.255) 78.486,93.255 ; 78.486,93.255 ccw(c78.904,93.255) 78.608,92.959 cw(c78.904,93.255) 78.486,93.255 ; 54.166,52.007 ccw(c53.558,52.614) 54.309,53.031 cw(c53.558,52.614) 54.166,52.007 ; 54.404,52.245 ccw(c53.864,52.784) 54.531,53.155 cw(c53.864,52.784) 54.404,52.245 ; 54.642,52.483 ccw(c54.17,52.954) 54.753,53.278 cw(c54.17,52.954) 54.642,52.483 ; R43.2@56.007,98.552 ccw(c56.007,99.686) 56.809,98.884 cw(c56.007,99.686) R43.2@56.007,98.552 ; R43.2@56.007,98.806 ccw(c56.007,100.553) 57.242,99.318 cw(c56.007,100.553) R43.2@56.007,98.806 ; R43.2@56.007,99.06 ccw(c56.007,101.42) 57.676,99.751 cw(c56.007,101.42) R43.2@56.007,99.06 ; U8.1@74.391,35.179 ccw(c75.236,35.179) 74.638,34.582 cw(c75.236,35.179) U8.1@74.391,35.179 ; v1@75.697,56.51 ccw(c75.486,56.721) 75.784,56.721 cw(c75.486,56.721) v1@75.697,56.51 ; 75.784,56.89 ccw(c76.321,56.89) 75.941,56.51 cw(c76.321,56.89) 75.784,56.89 ; R48.2@77.57,94.446 cw(c76.44,92.74) 78.486,92.74 ccw(c76.44,92.74) R48.2@77.57,94.446 ; R48.2@77.711,94.657 cw(c76.754,93.213) 78.486,93.213 ccw(c76.754,93.213) R48.2@77.711,94.657 ; R48.2@77.851,94.869 cw(c77.067,93.686) 78.486,93.686 ccw(c77.067,93.686) R48.2@77.851,94.869 ; 77.882,39.102 cw(c78.627,39.102) 78.1,39.629 ccw(c78.627,39.102) 77.882,39.102 ; R48.2@77.991,95.081 cw(c77.381,94.159) 78.486,94.159 ccw(c77.381,94.159) R48.2@77.991,95.081 ; v1@78.003,39.67 cw(c77.067,38.735) 78.39,38.735 ccw(c77.067,38.735) v1@78.003,39.67 ; 78.436,39.237 cw(c77.934,38.735) 78.644,38.735 ccw(c77.934,38.735) 78.436,39.237 ; U10.1@78.87,38.803 cw(c78.801,38.735) 78.898,38.735 ccw(c78.801,38.735) U10.1@78.87,38.803 ; v1@83.698,56.383 ccw(c83.489,56.592) 83.784,56.592 cw(c83.489,56.592) v1@83.698,56.383 ; 83.784,56.766 ccw(c84.325,56.766) 83.942,56.383 cw(c84.325,56.766) 83.784,56.766 ; v1@89.159,60.076 cw(c88.856,59.773) 89.284,59.773 ccw(c88.856,59.773) v1@89.159,60.076 ; 89.284,59.788 cw(c89.691,59.788) 89.403,60.076 ccw(c89.691,59.788) 89.284,59.788
  Bottom Layer w0.254: 4.1@33.02,37.084 34.798,35.306 36.576,35.306 C60.2@36.83,35.56 ; C59.2@36.83,33.528 C60.2@36.83,35.56 ; U13.18@42.87,38.619 U13.17@42.87,37.969 42.776,37.875 41.965,37.875 40.259,36.169 40.259,34.767 40.036,34.544 38.196,34.544 37.18,35.56 C60.2@36.83,35.56 ; J10.5@52.959,86.36 54.356,87.757 56.099,87.757 56.48,88.138 L5.1@67.691,88.138 ; J12.3@54.864,62.484 54.864,62.9 53.721,64.043 53.721,67.021 55.245,68.545 R36.1@55.245,71.501 R37.2@55.245,73.787 ; R24.1@69.977,33.02 69.977,34.798 C36.2@70.993,35.814 72.517,34.29 v1(74.93,34.29) ; C83.2@74.676,53.34 74.676,55.245 v1(75.819,56.388) ; C82.2@75.057,65.659 75.057,66.263 76.2,67.406 76.2,71.755 75.057,72.898 C81.2@75.057,73.279 75.057,73.883 76.2,75.026 76.2,76.835 75.057,77.978 C80.2@75.057,78.359 75.407,78.359 76.423,77.343 79.344,77.343 81.788,74.899 ; v1(75.819,60.452) 74.168,58.801 73.279,58.801 69.469,62.611 69.469,63.754 v1(71.247,65.532) 69.342,67.437 69.342,70.866 v1(71.12,72.644) 69.342,74.422 69.342,77.724 v1(70.993,79.375) 73.152,81.534 v1(79.248,81.534) 79.248,87.122 C79.2@80.391,88.265 78.486,90.17 v1(78.486,92.837) ; v1@75.999,60.452 77.002,59.449 82.572,59.449 v1@83.448,60.325 ; v1(77.978,39.751) 79.756,37.973 ; C46.2@80.518,37.973 79.756,37.973 ; C85.2@82.296,53.34 82.296,54.737 v1(83.82,56.261) ; v1@83.947,60.325 85.852,58.42 87.503,58.42 ; C84.2@87.376,53.34 v1(87.376,54.991) 87.376,58.293 87.503,58.42 ; C78.2@89.662,65.024 88.519,66.167 88.519,73.183 87.534,74.168 82.519,74.168 81.788,74.899 ; D7.1@100.965,60.452 100.965,61.056 99.822,62.199 99.822,64.262 R55.2@98.679,65.405 93.472,65.405 v1(92.075,64.008) ; 70.698,79.08 cw(c70.993,78.784) 70.993,79.202 ccw(c70.993,78.784) 70.698,79.08 ; 70.698,79.08 ccw(c70.402,79.375) 70.82,79.375 cw(c70.402,79.375) 70.698,79.08 ; 70.825,72.349 cw(c71.12,72.053) 71.12,72.471 ccw(c71.12,72.053) 70.825,72.349 ; 70.825,72.349 ccw(c70.529,72.644) v1@70.947,72.644 ; 70.825,72.349 ccw(c70.529,72.644) v1@70.947,72.644 ; 70.825,72.939 cw(c70.529,72.644) v1@70.947,72.644 ; 70.825,72.939 ccw(c71.12,73.235) 71.12,72.817 cw(c71.12,73.235) 70.825,72.939 ; 70.825,72.939 cw(c70.529,72.644) v1@70.947,72.644 ; 70.952,65.237 cw(c71.247,64.941) 71.247,65.359 ccw(c71.247,64.941) 70.952,65.237 ; 70.952,65.237 ccw(c70.656,65.532) v1@71.074,65.532 ; 70.952,65.237 ccw(c70.656,65.532) v1@71.074,65.532 ; 70.952,65.827 cw(c70.656,65.532) v1@71.074,65.532 ; 70.952,65.827 ccw(c71.247,66.123) 71.247,65.705 cw(c71.247,66.123) 70.952,65.827 ; 70.952,65.827 cw(c70.656,65.532) v1@71.074,65.532 ; 71.288,79.67 cw(c70.993,79.966) 70.993,79.548 ccw(c70.993,79.966) 71.288,79.67 ; 71.288,79.67 ccw(c71.584,79.375) 71.166,79.375 cw(c71.584,79.375) 71.288,79.67 ; 74.512,34.29 cw(c74.512,33.872) 74.808,34.168 ccw(c74.512,33.872) 74.512,34.29 ; 74.512,34.29 ccw(c74.512,34.708) 74.808,34.412 cw(c74.512,34.708) 74.512,34.29 ; 75.524,56.093 cw(c75.819,55.797) 75.819,56.215 ccw(c75.819,55.797) 75.524,56.093 ; 75.524,56.093 ccw(c75.228,56.388) 75.646,56.388 cw(c75.228,56.388) 75.524,56.093 ; 75.524,60.157 cw(c75.819,59.861) 75.819,60.279 ccw(c75.819,59.861) 75.524,60.157 ; 75.524,60.157 ccw(c75.228,60.452) 75.646,60.452 cw(c75.228,60.452) 75.524,60.157 ; 78.273,39.456 cw(c78.569,39.751) 78.151,39.751 ccw(c78.569,39.751) 78.273,39.456 ; 78.273,39.456 ccw(c77.978,39.16) 77.978,39.578 cw(c77.978,39.16) 78.273,39.456 ; 78.486,92.419 cw(c78.904,92.419) 78.608,92.715 ccw(c78.904,92.419) 78.486,92.419 ; 78.486,92.419 ccw(c78.068,92.419) 78.364,92.715 cw(c78.068,92.419) 78.486,92.419 ; 78.83,81.534 cw(c78.83,81.116) 79.126,81.412 ccw(c78.83,81.116) 78.83,81.534 ; 78.83,81.534 ccw(c78.83,81.952) v1@79.126,81.656 ; 78.83,81.534 ccw(c78.83,81.952) v1@79.126,81.656 ; v1@79.126,81.656 ccw(c78.83,81.952) 79.248,81.952 ; v1@79.126,81.656 ccw(c78.83,81.952) 79.248,81.952 ; 79.248,81.952 ccw(c79.666,81.952) 79.37,81.656 cw(c79.666,81.952) 79.248,81.952 ; 79.756,37.973 cw(c79.756,37.656) 80.049,37.778 ccw(c79.756,37.656) 79.756,37.973 ; 79.756,37.973 ccw(c79.756,38.29) 80.049,38.168 cw(c79.756,38.29) 79.756,37.973 ; 81.788,74.899 81.788,76.739 82.011,76.962 86.741,76.962 L2.1@87.884,78.105 89.027,76.962 91.747,76.962 91.92,77.135 92.484,77.135 92.883,76.736 92.883,66.774 92.075,65.966 v1(92.075,64.008) ; 83.525,55.966 cw(c83.82,55.67) 83.82,56.088 ccw(c83.82,55.67) 83.525,55.966 ; 83.525,55.966 ccw(c83.229,56.261) 83.647,56.261 cw(c83.229,56.261) 83.525,55.966 ; 87.376,54.573 cw(c87.794,54.573) 87.498,54.869 ccw(c87.794,54.573) 87.376,54.573 ; 87.376,54.573 ccw(c86.958,54.573) 87.254,54.869 cw(c86.958,54.573) 87.376,54.573 ; 87.376,55.409 cw(c86.958,55.409) 87.254,55.113 ccw(c86.958,55.409) 87.376,55.409 ; 87.376,55.409 ccw(c87.794,55.409) 87.498,55.113 cw(c87.794,55.409) 87.376,55.409 ; 87.503,58.42 v1(89.281,60.198) 89.997,60.914 92.484,60.914 92.883,61.313 92.883,62.738 92.075,63.546 v1(92.075,64.008) ; L2.1@87.884,77.47 ccw(c87.884,75.937) 86.8,77.021 cw(c87.884,75.937) L2.1@87.884,77.47 ; L2.1@87.884,77.47 cw(c87.884,75.937) 88.968,77.021 ccw(c87.884,75.937) L2.1@87.884,77.47 ; L2.1@87.884,77.724 ccw(c87.884,76.804) 87.234,77.455 cw(c87.884,76.804) L2.1@87.884,77.724 ; L2.1@87.884,77.724 cw(c87.884,76.804) 88.534,77.455 ccw(c87.884,76.804) L2.1@87.884,77.724 ; 88.986,59.903 cw(c89.281,59.607) 89.281,60.025 ccw(c89.281,59.607) 88.986,59.903 ; 88.986,59.903 ccw(c88.69,60.198) 89.108,60.198 cw(c88.69,60.198) 88.986,59.903 ; 89.576,60.493 cw(c89.281,60.789) 89.281,60.371 ccw(c89.281,60.789) 89.576,60.493 ; 89.576,60.493 ccw(c89.872,60.198) 89.454,60.198 cw(c89.872,60.198) 89.576,60.493 ; 92.075,63.59 cw(c92.493,63.59) 92.197,63.886 ccw(c92.493,63.59) 92.075,63.59 ; 92.075,63.59 ccw(c91.657,63.59) 91.953,63.886 cw(c91.657,63.59) 92.075,63.59 ; 92.075,64.426 cw(c91.657,64.426) 91.953,64.13 ccw(c91.657,64.426) 92.075,64.426 ; 92.075,64.426 ccw(c92.493,64.426) 92.197,64.13 cw(c92.493,64.426) 92.075,64.426 ; 92.37,64.303 cw(c92.075,64.599) 92.075,64.181 ccw(c92.075,64.599) 92.37,64.303 ; 92.37,64.303 ccw(c92.666,64.008) 92.248,64.008 cw(c92.666,64.008) 92.37,64.303 ; 41.88,37.791 cw(c42.195,37.476) 42.195,37.921 ccw(c42.195,37.476) 41.88,37.791 ; C80.2@75.184,78.359 ccw(c75.826,78.16) 75.351,77.684 cw(c75.826,78.16) C80.2@75.184,78.359 ; C80.2@75.427,78.284 ccw(c76.281,78.019) 75.648,77.387 cw(c76.281,78.019) C80.2@75.427,78.284 ; C80.2@75.669,78.209 ccw(c76.735,77.878) 75.946,77.089 cw(c76.735,77.878) C80.2@75.669,78.209 ; 87.107,77.328 ccw(c86.456,77.978) 87.376,77.978 cw(c86.456,77.978) 87.107,77.328 ; L2.1@88.392,77.978 ccw(c89.312,77.978) 88.661,77.328 cw(c89.312,77.978) L2.1@88.392,77.978
  other v1: 83.693,60.325
3V3-ISO: C35.1 C37.1 R24.2 U8.8 U9.4 U9.16 | length 41.6
  Top Layer w0.254: U9.16@58.593,33.401 59.891,33.401 63.112,36.622 63.754,36.622 U9.4@64.343,37.211 65.278,37.211 ; v1(66.929,34.417) 67.691,35.179 U8.8@68.143,35.179 ; 59.561,33.401 cw(c59.561,33.819) 59.265,33.523 ccw(c59.561,33.819) 59.561,33.401 ; 59.561,33.401 ccw(c59.561,32.983) 59.265,33.279 cw(c59.561,32.983) 59.561,33.401 ; 65.278,37.211 cw(c65.278,37.553) 65.022,37.326 ccw(c65.278,37.553) 65.278,37.211 ; 65.278,37.211 ccw(c65.278,36.869) 65.022,37.096 cw(c65.278,36.869) 65.278,37.211 ; 65.278,37.211 v1(65.786,37.719) ; 65.491,37.424 cw(c65.786,37.128) 65.786,37.546 ccw(c65.786,37.128) 65.491,37.424 ; 65.491,37.424 ccw(c65.195,37.719) 65.613,37.719 cw(c65.195,37.719) 65.491,37.424 ; v1(65.786,37.719) cw(c64.972,38.533) 64.903,37.384 ccw(c64.972,38.533) v1(65.786,37.719) ; 67.224,34.712 cw(c66.929,35.008) 66.929,34.59 ccw(c66.929,35.008) 67.224,34.712 ; 67.224,34.712 ccw(c67.52,34.417) 67.102,34.417 cw(c67.52,34.417) 67.224,34.712 ; U9.4@64.888,37.13 ccw(c64.927,37.779) 65.386,37.319 cw(c64.927,37.779) U9.4@64.888,37.13
  Bottom Layer w0.254: v1(65.786,37.719) C35.1@62.738,37.719 C37.1@62.738,35.179 63.5,34.417 v1(66.929,34.417) 67.691,33.655 R24.2@67.691,33.02 ; 65.368,37.719 cw(c65.368,37.301) 65.664,37.597 ccw(c65.368,37.301) 65.368,37.719 ; 65.368,37.719 ccw(c65.368,38.137) 65.664,37.841 cw(c65.368,38.137) 65.368,37.719 ; 66.511,34.417 cw(c66.511,33.999) 66.807,34.295 ccw(c66.511,33.999) 66.511,34.417 ; 66.511,34.417 ccw(c66.511,34.835) 66.807,34.539 cw(c66.511,34.835) 66.511,34.417 ; 67.224,34.122 cw(c67.52,34.417) 67.102,34.417 ccw(c67.52,34.417) 67.224,34.122 ; 67.224,34.122 ccw(c66.929,33.826) 66.929,34.244 cw(c66.929,33.826) 67.224,34.122 ; v1@66.887,34.459 cw(c65.788,33.36) 67.315,33.068 ccw(c65.788,33.36) v1@66.887,34.459 ; 67.226,34.12 cw(c66.357,33.251) 67.564,33.02 ccw(c66.357,33.251) 67.226,34.12 ; 67.565,33.781 cw(c66.926,33.142) 67.813,32.972 ccw(c66.926,33.142) 67.565,33.781
3V3_ISO: C43.1 C47.1 U10.8 U11.3 | length 25.4
  Top Layer w0.254: U10.8@84.638,38.735 v1@84.638,39.68 ; v1(87.122,35.814) 87.376,36.068 U11.3@88.336,36.068 ; 84.638,39.153 cw(c84.22,39.153) 84.516,38.857 ccw(c84.22,39.153) 84.638,39.153 ; 84.638,39.153 ccw(c85.056,39.153) 84.76,38.857 cw(c85.056,39.153) 84.638,39.153 ; 87.543,36.068 cw(c87.543,35.65) 87.839,35.946 ccw(c87.543,35.65) 87.543,36.068 ; 87.543,36.068 ccw(c87.543,36.486) 87.839,36.19 cw(c87.543,36.486) 87.543,36.068 ; 84.638,39.162 cw(c85.298,39.162) 84.831,39.629 ccw(c85.298,39.162) 84.638,39.162 ; v1@87.065,35.871 cw(c87.54,35.396) 87.54,36.068 ccw(c87.54,35.396) v1@87.065,35.871 ; v1@87.244,35.692 cw(c88.153,34.783) 88.153,36.068 ccw(c88.153,34.783) v1@87.244,35.692
  Bottom Layer w0.254: C47.1@82.804,37.973 82.931,37.973 v1(84.709,39.751) 84.783,39.751 87.122,37.412 v1(87.122,35.814) 89.027,37.719 C43.1@91.186,37.719 ; 84.414,39.456 cw(c84.709,39.16) 84.709,39.578 ccw(c84.709,39.16) 84.414,39.456 ; 84.414,39.456 ccw(c84.118,39.751) 84.536,39.751 cw(c84.118,39.751) 84.414,39.456 ; 87.122,36.232 cw(c86.704,36.232) 87,35.936 ccw(c86.704,36.232) 87.122,36.232 ; 87.122,36.232 ccw(c87.54,36.232) 87.244,35.936 cw(c87.54,36.232) 87.122,36.232 ; 87.417,36.109 cw(c87.122,36.405) 87.122,35.987 ccw(c87.122,36.405) 87.417,36.109 ; 87.417,36.109 ccw(c87.713,35.814) 87.295,35.814 cw(c87.713,35.814) 87.417,36.109
5V: 1.1 C56.2 C64.2 R46.2 U13.5 U13.6 U13.11 U13.12 | length 43.8
  Bottom Layer w0.254: R46.2@36.83,48.26 37.18,48.26 38.196,49.276 41.021,49.276 47.339,42.958 47.339,42.939 47.759,42.519 U13.5@48.57,42.519 ; U13.11@48.57,38.619 U13.12@48.57,37.969 48.574,37.973 C64.2@51.562,37.973 53.086,39.497 53.086,41.91 54.229,43.053 ; U13.6@48.57,41.869 U13.5@48.57,42.519 ; 1.1@55.88,44.704 54.229,43.053 ; U13.5@48.57,42.519 51.028,42.519 C56.2@51.562,43.053 54.229,43.053 ; 47.58,42.697 ccw(c47.895,43.012) 47.895,42.567 cw(c47.895,43.012) 47.58,42.697 ; U13.5@49.353,42.519 ccw(c49.353,45.135) 51.203,43.285 cw(c49.353,45.135) U13.5@49.353,42.519 ; 49.966,42.519 ccw(c49.966,44.522) 51.382,43.106 cw(c49.966,44.522) 49.966,42.519 ; 50.579,42.519 ccw(c50.579,43.909) 51.562,42.926 cw(c50.579,43.909) 50.579,42.519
